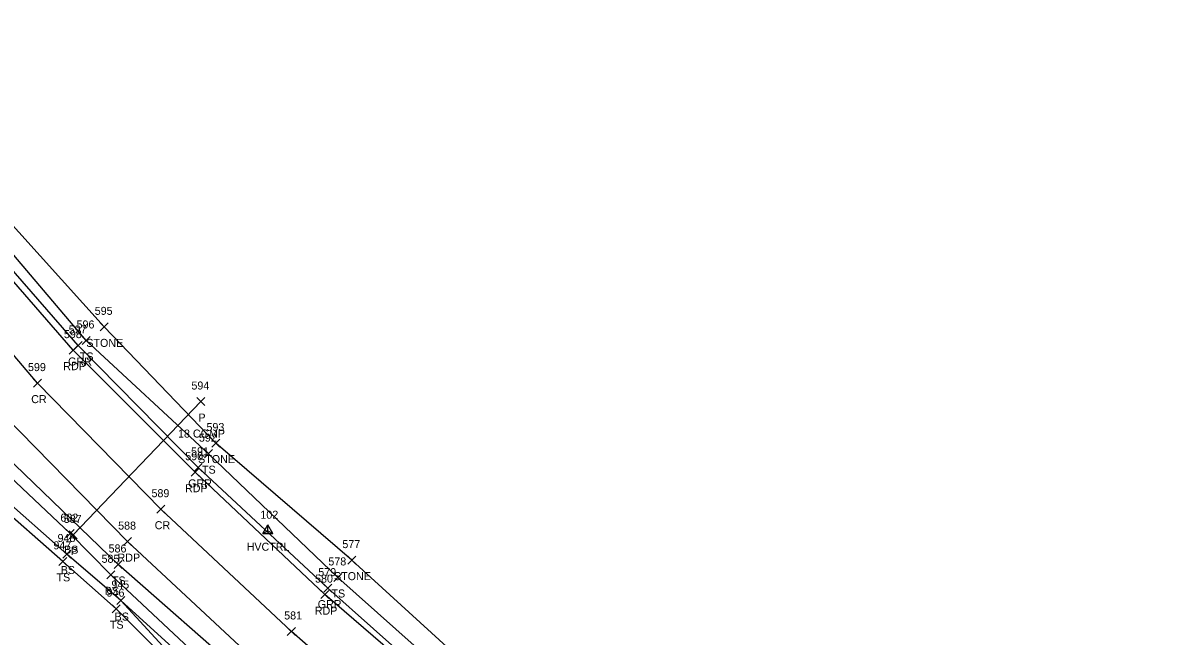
# Model space of a CAD drawing. Extents: x 1879695 to 1880991, y 836466 to 845172.
# Drawn here: x 1879991.4 to 1880274.2, y 844222.2 to 844375.4 of the extents above; entities that cross this region are included whole.
import ezdxf

# ---------------------------------------------------------------- set-up
doc = ezdxf.new("R2010")
doc.units = 0
for name, color, linetype in [('C_A', 7, 'Continuous'), ('C_I', 7, 'Continuous'), ('CPSM', 7, 'Continuous'), ('D_A', 7, 'Continuous'), ('D_C', 7, 'Continuous'), ('D_I', 7, 'Continuous'), ('D_TIC', 7, 'Continuous'), ('DCP', 7, 'Continuous'), ('L_A', 7, 'Continuous'), ('L_I', 7, 'Continuous'), ('L_TIC', 7, 'Continuous'), ('LASF', 7, 'Continuous'), ('LELB', 7, 'Continuous'), ('P_A', 7, 'Continuous'), ('P_I', 7, 'Continuous'), ('P_TIC', 7, 'Continuous'), ('PET', 7, 'Continuous'), ('PRC', 7, 'Continuous'), ('R_A', 7, 'Continuous'), ('R_I', 7, 'Continuous'), ('R_TIC', 7, 'Continuous'), ('RGR', 7, 'Continuous')]:
    doc.layers.add(name, color=color, linetype=linetype)

msp = doc.modelspace()

# ---------------------------------------------------------------- linework, layer by layer
at = {"layer": 'CPSM'}
for p, q in [((1880051.46, 844247.83), (1880052.71, 844249.99)), ((1880051.46, 844247.83), (1880052.71, 844248.55)), ((1880053.96, 844247.83), (1880052.71, 844249.99)), ((1880052.71, 844248.55), (1880052.71, 844249.99)), ((1880052.71, 844248.55), (1880052.71, 844248.55)), ((1880052.71, 844248.55), (1880053.96, 844247.83)), ((1880051.46, 844247.83), (1880053.96, 844247.83))]:
    msp.add_line(p, q, dxfattribs=at)
at = {"layer": 'D_TIC'}
for points in [[(1880034.96, 844279.81), (1880036.96, 844281.81)], [(1880036.96, 844279.81), (1880034.96, 844281.81)], [(1880003.08, 844246.5), (1880005.08, 844248.5)], [(1880005.08, 844246.5), (1880003.08, 844248.5)]]:
    msp.add_lwpolyline(points, dxfattribs=at)
at = {"layer": 'DCP'}
msp.add_lwpolyline([(1880004.08, 844247.5), (1880035.96, 844280.81)], dxfattribs=at)
at = {"layer": 'L_TIC'}
for points in [[(1880010.8, 844298.45), (1880012.8, 844300.45)], [(1880012.8, 844298.45), (1880010.8, 844300.45)], [(1880006.31, 844295.06), (1880008.31, 844297.06)], [(1880008.31, 844295.06), (1880006.31, 844297.06)], [(1880038.73, 844269.44), (1880040.73, 844271.44)], [(1880040.73, 844269.44), (1880038.73, 844271.44)], [(1880036.83, 844266.79), (1880038.83, 844268.79)], [(1880038.83, 844266.79), (1880036.83, 844268.79)], [(1880002.34, 844246.82), (1880004.34, 844248.82)], [(1880004.34, 844246.82), (1880002.34, 844248.82)], [(1880001.51, 844241.73), (1880003.51, 844243.73)], [(1880003.51, 844241.73), (1880001.51, 844243.73)], [(1880000.48, 844239.9), (1880002.48, 844241.9)], [(1880002.48, 844239.9), (1880000.48, 844241.9)], [(1880014.32, 844239.12), (1880016.32, 844241.12)], [(1880016.32, 844239.12), (1880014.32, 844241.12)], [(1880072.67, 844240.21), (1880074.67, 844242.21)], [(1880074.67, 844240.21), (1880072.67, 844242.21)], [(1880012.5, 844236.54), (1880014.5, 844238.54)], [(1880014.5, 844236.54), (1880012.5, 844238.54)], [(1880069.17, 844235.88), (1880071.17, 844237.88)], [(1880071.17, 844235.88), (1880069.17, 844237.88)], [(1880014.96, 844230.11), (1880016.96, 844232.11)], [(1880016.96, 844230.11), (1880014.96, 844232.11)], [(1880014.96, 844230.11), (1880016.96, 844232.11)], [(1880016.96, 844230.11), (1880014.96, 844232.11)], [(1880013.82, 844228.08), (1880015.82, 844230.08)], [(1880015.82, 844228.08), (1880013.82, 844230.08)]]:
    msp.add_lwpolyline(points, dxfattribs=at)
at = {"layer": 'LASF'}
msp.add_lwpolyline([(1880139.87, 844182.06), (1880107.81, 844210.08), (1880073.67, 844241.21), (1880039.73, 844270.44), (1880011.8, 844299.45), (1879985.05, 844328.99), (1879962.59, 844360.65), (1879939.31, 844397.46), (1879924.45, 844424.63), (1879917.02, 844424.23), (1879898.51, 844460.46), (1879892.86, 844475.33), (1879896.16, 844478.29), (1879889.96, 844497.62)], dxfattribs=at)
at = {"layer": 'LELB'}
for points in [[(1880237.65, 844030.17), (1880225.55, 844045.25), (1880203.19, 844067.94), (1880175.04, 844095.38), (1880141.55, 844124.24), (1880111.59, 844152.12), (1880079.67, 844179.09), (1880044.89, 844208.16), (1880013.5, 844237.54), (1880003.34, 844247.82), (1879979.16, 844270.62), (1879948.51, 844300.87), (1879928.97, 844335.67), (1879901.59, 844373.87), (1879881.39, 844405.75), (1879863.37, 844445.07), (1879846.41, 844479.41), (1879833.35, 844517.23), (1879821, 844560.9), (1879811.24, 844600.26), (1879800.64, 844646.71), (1879794.2, 844680.16), (1879792.03, 844683.6), (1879789.08, 844683.63)], [(1880243.53, 844023.94), (1880226.64, 844046.28), (1880204.68, 844069.12), (1880177.19, 844097.39), (1880144.15, 844127.37), (1880114.34, 844154.46), (1880082.65, 844181.38), (1880047.53, 844211.78), (1880015.32, 844240.12), (1879982.29, 844271.84), (1879951.96, 844303.04), (1879930.28, 844336.91), (1879904.08, 844374.32), (1879883.92, 844406.9), (1879866.98, 844446.02), (1879852.23, 844482.49), (1879838.68, 844519.35), (1879826.86, 844562.48), (1879815.22, 844600.52)], [(1880274.18, 844042.18), (1880252.69, 844068.34), (1880228.42, 844092.99), (1880199.77, 844120.37), (1880165.71, 844151.73), (1880135.43, 844177.69), (1880104.5, 844206.3), (1880070.17, 844236.88), (1880037.83, 844267.79), (1880007.31, 844296.06), (1879981.71, 844326.11), (1879957.94, 844357.83), (1879934.98, 844394.4), (1879917.02, 844424.23)], [(1880061.24, 844186.41), (1880044.41, 844199.51), (1880029.44, 844214.36), (1880014.82, 844229.08), (1880001.48, 844240.9), (1879983.99, 844256.18), (1879963.67, 844277.76), (1879939.18, 844304.48), (1879924.63, 844325.43), (1879894.06, 844369.68)], [(1880208.14, 844057.06), (1880205.3, 844059.71), (1880199.4, 844059.75), (1880191.54, 844071.18), (1880172.4, 844091.6), (1880168.93, 844094.5), (1880159.81, 844093.84), (1880155.76, 844086.44), (1880150.38, 844091.63), (1880154.09, 844106.65), (1880145.11, 844116.32), (1880126.55, 844133.72), (1880103.74, 844153.59), (1880081.3, 844171.15), (1880062.9, 844187.7), (1880046.08, 844200.5), (1880030.27, 844215.53), (1880015.96, 844231.11), (1880002.51, 844242.73), (1879985.64, 844257.52)], [(1880223.61, 844044.33), (1880209.51, 844057.91), (1880192.94, 844072.51), (1880173.59, 844092.48), (1880156.34, 844108.5), (1880145.52, 844117.21), (1880140.19, 844123.17), (1880127.57, 844134.43), (1880104.95, 844154.51), (1880082.15, 844172.53), (1880063.54, 844188.27), (1880047.18, 844201.5), (1880031.58, 844216.92), (1880015.96, 844231.11)]]:
    msp.add_lwpolyline(points, dxfattribs=at)
at = {"layer": 'P_TIC'}
for points in [[(1880003.09, 844292.64), (1880005.09, 844294.64)], [(1880005.09, 844292.64), (1880003.09, 844294.64)], [(1879994.14, 844284.41), (1879996.14, 844286.41)], [(1879996.14, 844284.41), (1879994.14, 844286.41)], [(1880033.5, 844262.16), (1880035.5, 844264.16)], [(1880035.5, 844262.16), (1880033.5, 844264.16)], [(1880024.99, 844252.92), (1880026.99, 844254.92)], [(1880026.99, 844252.92), (1880024.99, 844254.92)], [(1880016.65, 844244.83), (1880018.65, 844246.83)], [(1880018.65, 844244.83), (1880016.65, 844246.83)], [(1880065.94, 844231.59), (1880067.94, 844233.59)], [(1880067.94, 844231.59), (1880065.94, 844233.59)], [(1880057.56, 844222.39), (1880059.56, 844224.39)], [(1880059.56, 844222.39), (1880057.56, 844224.39)]]:
    msp.add_lwpolyline(points, dxfattribs=at)
at = {"layer": 'PET'}
for points in [[(1880269.75, 844039.67), (1880250.27, 844065.9), (1880225.97, 844090.31), (1880195.98, 844117.55), (1880162.1, 844148.13), (1880132.62, 844174.7), (1880101.36, 844203.03), (1880066.94, 844232.59), (1880034.5, 844263.16), (1880004.09, 844293.64), (1879978.17, 844323.39), (1879954.46, 844354.82), (1879930.76, 844391.37), (1879912.37, 844423.12), (1879894.17, 844458.9), (1879879.41, 844492.34), (1879865.46, 844529.81), (1879852.88, 844569.32), (1879843.17, 844608.03)], [(1880246.17, 844024.86), (1880229.35, 844048.54), (1880207.67, 844072.23), (1880179.65, 844099.99), (1880146.48, 844130.19), (1880116.3, 844156.76), (1880085.61, 844184.86), (1880050.42, 844215.32), (1880017.65, 844245.83), (1879986.99, 844277.13), (1879959.04, 844308.59), (1879934.2, 844340.79), (1879910.26, 844378.73), (1879891.14, 844411.43), (1879872.36, 844448.44), (1879856.33, 844484.43), (1879842.37, 844521.56), (1879829.6, 844563.28), (1879820.43, 844602.23)]]:
    msp.add_lwpolyline(points, dxfattribs=at)
at = {"layer": 'PRC'}
msp.add_lwpolyline([(1880256.85, 844032.04), (1880238.91, 844056.2), (1880216.7, 844080.65), (1880187.27, 844108.93), (1880154.23, 844138.82), (1880124.19, 844165.48), (1880092.74, 844193.41), (1880058.56, 844223.39), (1880025.99, 844253.92), (1879995.14, 844285.41), (1879968.79, 844316.24), (1879945.09, 844347.91), (1879920.67, 844385.19), (1879902.45, 844417.14), (1879883.72, 844454.21), (1879868.53, 844488.38), (1879854.47, 844526.01), (1879841.81, 844566.38), (1879832.13, 844605)], dxfattribs=at)
at = {"layer": 'R_TIC'}
for points in [[(1880004.3, 844293.8), (1880006.3, 844295.8)], [(1880006.3, 844293.8), (1880004.3, 844295.8)], [(1880034.3, 844263.37), (1880036.3, 844265.37)], [(1880036.3, 844263.37), (1880034.3, 844265.37)], [(1880066.67, 844233.21), (1880068.67, 844235.21)], [(1880068.67, 844233.21), (1880066.67, 844235.21)]]:
    msp.add_lwpolyline(points, dxfattribs=at)
at = {"layer": 'RGR'}
msp.add_lwpolyline([(1880270.9, 844040.93), (1880251.09, 844066.69), (1880226.93, 844091.38), (1880197.34, 844118.12), (1880162.87, 844149.15), (1880133.45, 844175.62), (1880101.92, 844203.72), (1880067.67, 844234.21), (1880035.3, 844264.37), (1880005.3, 844294.8), (1879979.45, 844324.37), (1879956.29, 844356.24), (1879932.57, 844392.56), (1879914.54, 844423.96), (1879896.38, 844459.86), (1879881.66, 844493.03), (1879867.6, 844530.61), (1879855.21, 844570.01), (1879845.36, 844608.98)], dxfattribs=at)

# ---------------------------------------------------------------- texts
at = {"layer": 'C_A'}
msp.add_text('HVCTRL', height=2, dxfattribs=at).set_placement((1880047.4, 844243.55))
at = {"layer": 'C_I'}
msp.add_text('102', height=2, dxfattribs=at).set_placement((1880050.83, 844251.55))
at = {"layer": 'D_A'}
for p in [(1880035.34, 844275.81), (1880003.45, 844242.5)]:
    msp.add_text('P', height=2, dxfattribs=at).set_placement(p)
at = {"layer": 'D_C'}
msp.add_text('18 CGMP', height=2, dxfattribs=at).set_placement((1880030.25, 844271.81))
at = {"layer": 'D_I'}
for s, p in [('594', (1880033.6, 844283.81)), ('587', (1880001.71, 844250.5))]:
    msp.add_text(s, height=2, dxfattribs=at).set_placement(p)
at = {"layer": 'L_A'}
for s, p in [('STONE', (1880007.34, 844294.45)), ('TS', (1880005.72, 844291.06)), ('STONE', (1880035.27, 844265.44)), ('TS', (1880036.24, 844262.79)), ('BS', (1880001.79, 844242.82)), ('BS', (1880000.95, 844237.73)), ('TS', (1879999.89, 844235.9)), ('TS', (1880013.73, 844235.12)), ('STONE', (1880069.22, 844236.21)), ('BS', (1880011.94, 844232.54)), ('TS', (1880068.58, 844231.88)), ('TS', (1880013.23, 844224.08)), ('BS', (1880014.41, 844226.11)), ('BS', (1880014.41, 844226.11))]:
    msp.add_text(s, height=2, dxfattribs=at).set_placement(p)
at = {"layer": 'L_I'}
for s, p in [('595', (1880009.44, 844302.45)), ('596', (1880004.9, 844299.06)), ('593', (1880037.36, 844273.44)), ('592', (1880035.47, 844270.79)), ('602', (1880000.86, 844250.82)), ('947', (1879999.12, 844243.9)), ('948', (1880000.15, 844245.73)), ('577', (1880071.31, 844244.21)), ('585', (1880011.14, 844240.54)), ('586', (1880012.9, 844243.12)), ('578', (1880067.81, 844239.88)), ('946', (1880012.4, 844232.08)), ('945', (1880013.6, 844234.11)), ('945', (1880013.6, 844234.11))]:
    msp.add_text(s, height=2, dxfattribs=at).set_placement(p)
at = {"layer": 'P_A'}
for s, p in [('RDP', (1880001.58, 844288.64)), ('CR', (1879993.57, 844280.41)), ('RDP', (1880031.99, 844258.16)), ('CR', (1880024.43, 844248.92)), ('RDP', (1880015.14, 844240.83)), ('RDP', (1880064.42, 844227.59))]:
    msp.add_text(s, height=2, dxfattribs=at).set_placement(p)
at = {"layer": 'P_I'}
for s, p in [('598', (1880001.73, 844296.64)), ('599', (1879992.77, 844288.41)), ('590', (1880032.05, 844266.16)), ('589', (1880023.62, 844256.92)), ('588', (1880015.29, 844248.83)), ('580', (1880064.49, 844235.59)), ('581', (1880056.77, 844226.39))]:
    msp.add_text(s, height=2, dxfattribs=at).set_placement(p)
at = {"layer": 'R_A'}
for p in [(1880002.79, 844289.8), (1880032.79, 844259.37), (1880065.16, 844229.21)]:
    msp.add_text('GRR', height=2, dxfattribs=at).set_placement(p)
at = {"layer": 'R_I'}
for s, p in [('597', (1880002.94, 844297.8)), ('591', (1880033.51, 844267.37)), ('579', (1880065.3, 844237.21))]:
    msp.add_text(s, height=2, dxfattribs=at).set_placement(p)

doc.saveas('drawing.dxf')
